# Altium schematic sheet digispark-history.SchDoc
size 199 x 160 mm
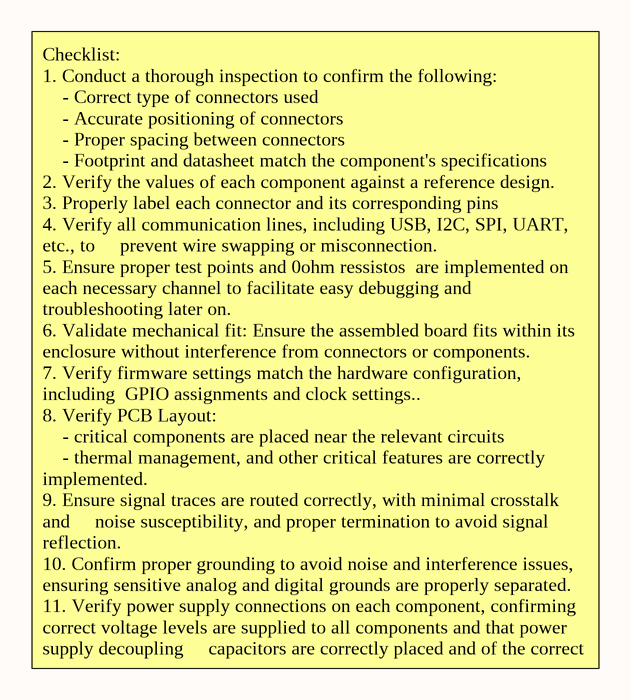
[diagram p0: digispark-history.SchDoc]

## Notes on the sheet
- Checklist:
  1. Conduct a thorough inspection to confirm the following:
  - Correct type of connectors used
  - Accurate positioning of connectors
  - Proper spacing between connectors
  - Footprint and datasheet match the component's specifications
  2. Verify the values of each component against a reference design.
  3. Properly label each connector and its corresponding pins
  4. Verify all communication lines, including USB, I2C, SPI, UART, etc., to     prevent wire swapping or misconnection.
  5. Ensure proper test points and 0ohm ressistos  are implemented on each necessary channel to facilitate easy debugging and troubleshooting later on.
  6. Validate mechanical fit: Ensure the assembled board fits within its     enclosure without interference from connectors or components.
  7. Verify firmware settings match the hardware configuration,   including  GPIO assignments and clock settings..
  8. Verify PCB Layout:
  - critical components are placed near the relevant circuits
  - thermal management, and other critical features are correctly          implemented.
  9. Ensure signal traces are routed correctly, with minimal crosstalk and     noise susceptibility, and proper termination to avoid signal reflection.
  10. Confirm proper grounding to avoid noise and interference issues,     ensuring sensitive analog and digital grounds are properly separated.
  11. Verify power supply connections on each component, confirming correct voltage levels are supplied to all components and that power supply decoupling     capacitors are correctly placed and of the correct value.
